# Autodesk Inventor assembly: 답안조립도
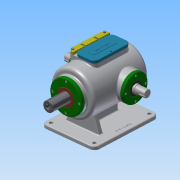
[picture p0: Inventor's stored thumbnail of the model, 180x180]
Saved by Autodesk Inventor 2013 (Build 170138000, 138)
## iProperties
Created: 2018-08
Part Number: 답안조립도
Document SubType Name: Assembly
Designer: Administrator
Mass: 7433.62 g
Surface Area: 4486.61 cm^2
Volume: 2026.97 cm^3
Density: 3.66735 g/cm^3
Author: Administrator
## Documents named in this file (15)
- C:\Users\Administrator\Desktop\380808V1023\공용부품_20180825_1\답안조립도.iam
- C:\Users\Administrator\Desktop\380808V1023\공용부품_20180825_1\본체.ipt
- C:\Users\Administrator\Desktop\380808V1023\공용부품_20180825_1\편심축.ipt
- C:\Users\Administrator\Desktop\380808V1023\공용부품_20180825_1\베어링 6205.ipt
- 베어링 6205.ipt
- C:\Users\Administrator\Desktop\380808V1023\공용부품_20180825_1\축 커버.ipt
- C:\Users\Administrator\Desktop\380808V1023\공용부품_20180825_1\오일 실 25 38 8.ipt
- C:\Users\Administrator\Desktop\380808V1023\공용부품_20180825_1\슬라이드.ipt
- C:\Users\Administrator\Desktop\380808V1023\공용부품_20180825_1\슬라이드 커버.ipt
- C:\Users\Administrator\Desktop\380808V1023\공용부품_20180825_1\부시.ipt
- C:\Users\Administrator\Desktop\380808V1023\공용부품_20180825_1\상부커버.ipt
- C:\Users\Administrator\Desktop\380808V1023\공용부품_20180825_1\고정플레이트.ipt
- C:\Users\Administrator\Desktop\380808V1023\공용부품_20180825_1\볼트 M4x0.7.ipt
- C:\Users\Administrator\Desktop\380808V1023\공용부품_20180825_1\육각머리볼트 M4.ipt
- C:\Users\Administrator\Desktop\380808V1023\공용부품_20180825_1\가변스프링.ipt
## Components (14 placed, 3 different names)
1. 고정플레이트:1
2. M4x0.7:1
3. M4x0.7:2
4. M4x0.7:3
5. M4x0.7:4
6. M4x0.7:5
7. M4x0.7:6
8. M4x0.7:7
9. M4x0.7:8
10. M4x0.7:9
11. M4x0.7:10
12. M4x0.7:11
13. M4x0.7:12
14. 가변스프링:1
